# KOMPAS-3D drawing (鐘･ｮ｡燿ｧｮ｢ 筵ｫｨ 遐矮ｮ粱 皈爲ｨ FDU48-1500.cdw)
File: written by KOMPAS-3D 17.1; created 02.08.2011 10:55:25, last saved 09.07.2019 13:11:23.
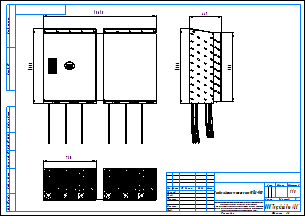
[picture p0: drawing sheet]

Title block, sheet 1: name: Преобразователи частоты серии FDU48-1500; scale: 1:10; sheets: 1; sheet format: A3; stored path: \\adlc.lan\data\АДЛ_ПКД\3D-модели\Поставщики\Оборудование Emotron\Преобразователи частоты\Серия FDU 2.0\KOMPAS 2D\Преобразователи частоты серии FDU48-1500.cdw

Views: Спереди 1
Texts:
  Рама для чертежей
  Лит-Масса-Масштаб
  Материал-Предприятие
  Масштаб
  Изм.
  Лист
  № докум.
  Подп.
  Дата
  Лит.
  Разраб.
  Пров.
  Т.контр.
  Листов
  Внимание! Данный продукт является объектом авторского права ООО «Торговый Дом АДЛ».
  Запрещается изменение, копирование, распространение
  (в том числе путем копирования на другие сайты и ресурсы в Интернете)
  или любое иное использование информации и объектов без предварительного
  согласия правообладателя (ООО «Торговый Дом АДЛ»).
  Н.контр.
  Утв.
  ООО "Торговый дом АДЛ"
  Изменение
  Номер документа
  Подпись
  Обозначение документа
  Наименование изделия
  Масса изделия по ГОСТ 2.109-73
  Порядковый номер листа
  Общее количество листов в документе
  Характер работы, выполненной лицом, подписавшим документ
  Наименование или индекс предприятия, выпускающего документ
  Инв. № подл.
  Подп. и дата
  Взам. инв. №
  Инв. № дубл.
  Инвентарный номер подлинника по ГОСТ 2.501-68
  Подпись принявшего подлинник в отдел технической документации
  Инвентарный номер подлинника, взамен которого выпущен данный подлинник
  Инвентарный номер дубликата по ГОСТ 2.502-68
  Подпись принявшего дубликат в отдел технической документации
  Справ. №
  Перв. примен.
  Обозначение документа, взамен или на основании которого выпущен данный документ
  Обозначение документа, в котором впервые записан данный документ
  Подпись лица, копировавшего чертеж
  Обозначение формата листа
  !Рама для чертежа
Dimensions and other numbers on the sheet: 1561,5; 1036; 449; 956; 730; 1:10; 1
